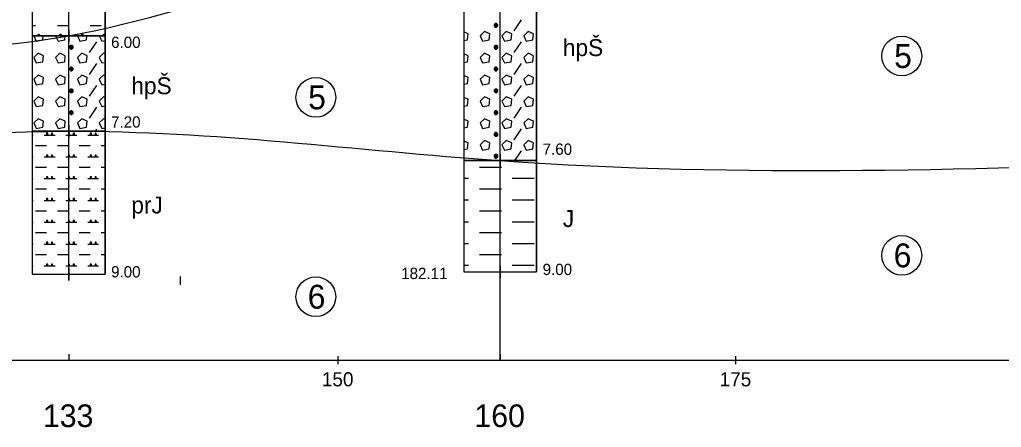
# Model space of a CAD drawing. Extents: x 3042 to 4120, y 576 to 2694.
# Drawn here: x 3349 to 3410.7, y 982.5 to 1008.1 of the extents above; entities that cross this region are included whole.
import ezdxf

# ---------------------------------------------------------------- set-up
doc = ezdxf.new("R2010")
doc.units = 0
for name, color, linetype in [('14', 7, 'Continuous'), ('17', 7, 'Continuous'), ('18', 7, 'Continuous'), ('51', 7, 'Continuous'), ('52', 7, 'Continuous'), ('53', 7, 'Continuous'), ('56', 7, 'Continuous'), ('7', 7, 'Continuous'), ('pomocna', 7, 'Continuous'), ('rozhraní', 7, 'Continuous')]:
    doc.layers.add(name, color=color, linetype=linetype)

msp = doc.modelspace()

# ---------------------------------------------------------------- linework, layer by layer
at = {"layer": '18'}
for p, q in [((3379.247, 992.267), (3379.247, 1037.267)), ((3352.127, 991.717), (3352.127, 1037.117)), ((3351.746, 992.117), (3352.508, 992.117)), ((3352.127, 992.498), (3352.127, 991.736)), ((3378.866, 992.267), (3379.628, 992.267)), ((3379.247, 992.648), (3379.247, 991.886)), ((3352.127, 992.098), (3352.127, 991.717)), ((3352.127, 987.098), (3352.127, 986.717)), ((3379.247, 987.098), (3379.247, 986.717))]:
    msp.add_line(p, q, dxfattribs=at)
at = {"layer": '51'}
for p, q in [((3378.977, 1007.656), (3378.977, 1007.884)), ((3380.12, 1007.427), (3380.578, 1008.113)), ((3378.977, 1006.284), (3378.977, 1006.513)), ((3380.12, 1006.055), (3380.578, 1006.741)), ((3378.977, 1004.912), (3378.977, 1005.141)), ((3380.12, 1004.684), (3380.578, 1005.37)), ((3380.12, 1003.312), (3380.578, 1003.998)), ((3378.977, 1003.541), (3378.977, 1003.769)), ((3380.12, 1001.941), (3380.578, 1002.626)), ((3378.977, 1002.169), (3378.977, 1002.398)), ((3378.977, 1000.798), (3378.977, 1001.026)), ((3380.12, 1000.569), (3380.578, 1001.255)), ((3378.977, 999.426), (3378.977, 999.655)), ((3380.167, 999.267), (3380.578, 999.883)), ((3377.949, 998.855), (3378.635, 998.855)), ((3378.635, 998.855), (3379.32, 998.855)), ((3376.961, 998.169), (3377.263, 998.169)), ((3380.006, 998.169), (3380.692, 998.169)), ((3380.692, 998.169), (3381.378, 998.169)), ((3377.949, 997.483), (3378.635, 997.483)), ((3378.635, 997.483), (3379.32, 997.483)), ((3376.961, 996.797), (3377.263, 996.797)), ((3380.006, 996.797), (3380.692, 996.797)), ((3380.692, 996.797), (3381.378, 996.797)), ((3377.949, 996.111), (3378.635, 996.111)), ((3378.635, 996.111), (3379.32, 996.111)), ((3376.961, 995.426), (3377.263, 995.426)), ((3380.006, 995.426), (3380.692, 995.426)), ((3380.692, 995.426), (3381.378, 995.426)), ((3377.949, 994.74), (3378.635, 994.74)), ((3378.635, 994.74), (3379.32, 994.74)), ((3376.961, 994.054), (3377.263, 994.054)), ((3380.006, 994.054), (3380.692, 994.054)), ((3380.692, 994.054), (3381.378, 994.054)), ((3377.949, 993.368), (3378.635, 993.368)), ((3378.635, 993.368), (3379.32, 993.368)), ((3376.961, 992.682), (3377.263, 992.682)), ((3380.006, 992.682), (3380.692, 992.682)), ((3380.692, 992.682), (3381.378, 992.682))]:
    msp.add_line(p, q, dxfattribs=at)
for points in [[(3376.961, 999.267), (3381.533, 999.267), (3381.533, 1013.767), (3376.961, 1013.767)], [(3349.841, 1007.117), (3354.413, 1007.117), (3354.413, 1013.117), (3349.841, 1013.117)], [(3349.841, 1001.117), (3354.413, 1001.117), (3354.413, 1007.117), (3349.841, 1007.117)], [(3349.841, 992.117), (3354.413, 992.117), (3354.413, 1001.117), (3349.841, 1001.117)], [(3376.961, 992.267), (3381.533, 992.267), (3381.533, 999.267), (3376.961, 999.267)]]:
    msp.add_lwpolyline(points, close=True, dxfattribs=at)
for points in [[(3349.841, 1007.77), (3350.049, 1007.77)], [(3351.421, 1007.77), (3352.107, 1007.77)], [(3353.478, 1007.77), (3354.164, 1007.77)], [(3378.939, 1007.884), (3378.863, 1007.808), (3378.863, 1007.732), (3378.939, 1007.656), (3379.016, 1007.656), (3379.092, 1007.732), (3379.092, 1007.808), (3379.016, 1007.884), (3378.939, 1007.884), (3379.092, 1007.732), (3378.863, 1007.732), (3379.016, 1007.884)], [(3349.937, 1007.117), (3350.087, 1006.779), (3350.506, 1006.856), (3350.532, 1007.117)], [(3350.202, 1007.198), (3350.125, 1007.122), (3350.125, 1007.117)], [(3350.196, 1007.117), (3350.278, 1007.198)], [(3350.354, 1007.117), (3350.354, 1007.122), (3350.278, 1007.198), (3350.202, 1007.198), (3350.283, 1007.117)], [(3350.24, 1007.117), (3350.24, 1007.198)], [(3351.309, 1007.117), (3351.459, 1006.779), (3351.878, 1006.856), (3351.904, 1007.117)], [(3351.573, 1007.198), (3351.497, 1007.122), (3351.497, 1007.117)], [(3351.568, 1007.117), (3351.649, 1007.198)], [(3351.726, 1007.117), (3351.726, 1007.122), (3351.649, 1007.198), (3351.573, 1007.198), (3351.655, 1007.117)], [(3351.611, 1007.117), (3351.611, 1007.198)], [(3352.68, 1007.117), (3352.83, 1006.779), (3353.25, 1006.856), (3353.276, 1007.117)], [(3352.945, 1007.198), (3352.869, 1007.122), (3352.869, 1007.117)], [(3352.94, 1007.117), (3353.021, 1007.198)], [(3353.097, 1007.117), (3353.097, 1007.122), (3353.021, 1007.198), (3352.945, 1007.198), (3353.026, 1007.117)], [(3352.983, 1007.117), (3352.983, 1007.198)], [(3354.052, 1007.117), (3354.202, 1006.779), (3354.413, 1006.818)], [(3354.316, 1007.198), (3354.24, 1007.122), (3354.24, 1007.117)], [(3354.311, 1007.117), (3354.393, 1007.198)], [(3354.413, 1007.178), (3354.393, 1007.198), (3354.316, 1007.198), (3354.398, 1007.117)], [(3354.354, 1007.117), (3354.354, 1007.198)], [(3376.961, 1006.814), (3377.187, 1006.856), (3377.225, 1007.237), (3376.961, 1007.354)], [(3377.987, 1007.122), (3378.139, 1006.779), (3378.558, 1006.856), (3378.596, 1007.237), (3378.254, 1007.389), (3377.987, 1007.122)], [(3379.358, 1007.122), (3379.511, 1006.779), (3379.93, 1006.856), (3379.968, 1007.237), (3379.625, 1007.389), (3379.358, 1007.122)], [(3380.73, 1007.122), (3380.882, 1006.779), (3381.302, 1006.856), (3381.34, 1007.237), (3380.997, 1007.389), (3380.73, 1007.122)], [(3352.259, 1006.513), (3352.183, 1006.436), (3352.183, 1006.36), (3352.259, 1006.284), (3352.335, 1006.284), (3352.411, 1006.36), (3352.411, 1006.436), (3352.335, 1006.513), (3352.259, 1006.513), (3352.411, 1006.36), (3352.183, 1006.36), (3352.335, 1006.513)], [(3352.297, 1006.284), (3352.297, 1006.513)], [(3353.44, 1006.055), (3353.897, 1006.741)], [(3378.939, 1006.513), (3378.863, 1006.436), (3378.863, 1006.36), (3378.939, 1006.284), (3379.016, 1006.284), (3379.092, 1006.36), (3379.092, 1006.436), (3379.016, 1006.513), (3378.939, 1006.513), (3379.092, 1006.36), (3378.863, 1006.36), (3379.016, 1006.513)], [(3349.935, 1005.751), (3350.087, 1005.408), (3350.506, 1005.484), (3350.544, 1005.865), (3350.202, 1006.017), (3349.935, 1005.751)], [(3351.306, 1005.751), (3351.459, 1005.408), (3351.878, 1005.484), (3351.916, 1005.865), (3351.573, 1006.017), (3351.306, 1005.751)], [(3352.678, 1005.751), (3352.83, 1005.408), (3353.25, 1005.484), (3353.288, 1005.865), (3352.945, 1006.017), (3352.678, 1005.751)], [(3354.413, 1005.975), (3354.316, 1006.017), (3354.05, 1005.751)], [(3354.05, 1005.751), (3354.202, 1005.408), (3354.413, 1005.446)], [(3376.961, 1005.443), (3377.187, 1005.484), (3377.225, 1005.865), (3376.961, 1005.982)], [(3377.987, 1005.751), (3378.139, 1005.408), (3378.558, 1005.484), (3378.596, 1005.865), (3378.254, 1006.017), (3377.987, 1005.751)], [(3379.358, 1005.751), (3379.511, 1005.408), (3379.93, 1005.484), (3379.968, 1005.865), (3379.625, 1006.017), (3379.358, 1005.751)], [(3380.73, 1005.751), (3380.882, 1005.408), (3381.302, 1005.484), (3381.34, 1005.865), (3380.997, 1006.017), (3380.73, 1005.751)], [(3352.259, 1005.141), (3352.183, 1005.065), (3352.183, 1004.989), (3352.259, 1004.912), (3352.335, 1004.912), (3352.411, 1004.989), (3352.411, 1005.065), (3352.335, 1005.141), (3352.259, 1005.141), (3352.411, 1004.989), (3352.183, 1004.989), (3352.335, 1005.141)], [(3352.297, 1004.912), (3352.297, 1005.141)], [(3353.44, 1004.684), (3353.897, 1005.37)], [(3378.939, 1005.141), (3378.863, 1005.065), (3378.863, 1004.989), (3378.939, 1004.912), (3379.016, 1004.912), (3379.092, 1004.989), (3379.092, 1005.065), (3379.016, 1005.141), (3378.939, 1005.141), (3379.092, 1004.989), (3378.863, 1004.989), (3379.016, 1005.141)], [(3349.935, 1004.379), (3350.087, 1004.036), (3350.506, 1004.112), (3350.544, 1004.493), (3350.202, 1004.646), (3349.935, 1004.379)], [(3351.306, 1004.379), (3351.459, 1004.036), (3351.878, 1004.112), (3351.916, 1004.493), (3351.573, 1004.646), (3351.306, 1004.379)], [(3352.678, 1004.379), (3352.83, 1004.036), (3353.25, 1004.112), (3353.288, 1004.493), (3352.945, 1004.646), (3352.678, 1004.379)], [(3354.413, 1004.603), (3354.316, 1004.646), (3354.05, 1004.379)], [(3376.961, 1004.071), (3377.187, 1004.112), (3377.225, 1004.493), (3376.961, 1004.611)], [(3377.987, 1004.379), (3378.139, 1004.036), (3378.558, 1004.112), (3378.596, 1004.493), (3378.254, 1004.646), (3377.987, 1004.379)], [(3379.358, 1004.379), (3379.511, 1004.036), (3379.93, 1004.112), (3379.968, 1004.493), (3379.625, 1004.646), (3379.358, 1004.379)], [(3380.73, 1004.379), (3380.882, 1004.036), (3381.302, 1004.112), (3381.34, 1004.493), (3380.997, 1004.646), (3380.73, 1004.379)], [(3353.44, 1003.312), (3353.897, 1003.998)], [(3354.05, 1004.379), (3354.202, 1004.036), (3354.413, 1004.074)], [(3349.935, 1003.007), (3350.087, 1002.665), (3350.506, 1002.741), (3350.544, 1003.122), (3350.202, 1003.274), (3349.935, 1003.007)], [(3351.306, 1003.007), (3351.459, 1002.665), (3351.878, 1002.741), (3351.916, 1003.122), (3351.573, 1003.274), (3351.306, 1003.007)], [(3352.259, 1003.769), (3352.183, 1003.693), (3352.183, 1003.617), (3352.259, 1003.541), (3352.335, 1003.541), (3352.411, 1003.617), (3352.411, 1003.693), (3352.335, 1003.769), (3352.259, 1003.769), (3352.411, 1003.617), (3352.183, 1003.617), (3352.335, 1003.769)], [(3352.297, 1003.541), (3352.297, 1003.769)], [(3352.678, 1003.007), (3352.83, 1002.665), (3353.25, 1002.741), (3353.288, 1003.122), (3352.945, 1003.274), (3352.678, 1003.007)], [(3354.413, 1003.231), (3354.316, 1003.274), (3354.05, 1003.007)], [(3376.961, 1002.7), (3377.187, 1002.741), (3377.225, 1003.122), (3376.961, 1003.239)], [(3377.987, 1003.007), (3378.139, 1002.665), (3378.558, 1002.741), (3378.596, 1003.122), (3378.254, 1003.274), (3377.987, 1003.007)], [(3378.939, 1003.769), (3378.863, 1003.693), (3378.863, 1003.617), (3378.939, 1003.541), (3379.016, 1003.541), (3379.092, 1003.617), (3379.092, 1003.693), (3379.016, 1003.769), (3378.939, 1003.769), (3379.092, 1003.617), (3378.863, 1003.617), (3379.016, 1003.769)], [(3379.358, 1003.007), (3379.511, 1002.665), (3379.93, 1002.741), (3379.968, 1003.122), (3379.625, 1003.274), (3379.358, 1003.007)], [(3380.73, 1003.007), (3380.882, 1002.665), (3381.302, 1002.741), (3381.34, 1003.122), (3380.997, 1003.274), (3380.73, 1003.007)], [(3353.44, 1001.941), (3353.897, 1002.626)], [(3354.05, 1003.007), (3354.202, 1002.665), (3354.413, 1002.703)], [(3352.259, 1002.398), (3352.183, 1002.322), (3352.183, 1002.245), (3352.259, 1002.169), (3352.335, 1002.169), (3352.411, 1002.245), (3352.411, 1002.322), (3352.335, 1002.398), (3352.259, 1002.398), (3352.411, 1002.245), (3352.183, 1002.245), (3352.335, 1002.398)], [(3352.297, 1002.169), (3352.297, 1002.398)], [(3378.939, 1002.398), (3378.863, 1002.322), (3378.863, 1002.245), (3378.939, 1002.169), (3379.016, 1002.169), (3379.092, 1002.245), (3379.092, 1002.322), (3379.016, 1002.398), (3378.939, 1002.398), (3379.092, 1002.245), (3378.863, 1002.245), (3379.016, 1002.398)], [(3349.935, 1001.636), (3350.087, 1001.293), (3350.506, 1001.369), (3350.544, 1001.75), (3350.202, 1001.903), (3349.935, 1001.636)], [(3351.306, 1001.636), (3351.459, 1001.293), (3351.878, 1001.369), (3351.916, 1001.75), (3351.573, 1001.903), (3351.306, 1001.636)], [(3352.678, 1001.636), (3352.83, 1001.293), (3353.25, 1001.369), (3353.288, 1001.75), (3352.945, 1001.903), (3352.678, 1001.636)], [(3354.413, 1001.86), (3354.316, 1001.903), (3354.05, 1001.636)], [(3354.05, 1001.636), (3354.202, 1001.293), (3354.413, 1001.331)], [(3376.961, 1001.328), (3377.187, 1001.369), (3377.225, 1001.75), (3376.961, 1001.868)], [(3377.987, 1001.636), (3378.139, 1001.293), (3378.558, 1001.369), (3378.596, 1001.75), (3378.254, 1001.903), (3377.987, 1001.636)], [(3379.358, 1001.636), (3379.511, 1001.293), (3379.93, 1001.369), (3379.968, 1001.75), (3379.625, 1001.903), (3379.358, 1001.636)], [(3380.73, 1001.636), (3380.882, 1001.293), (3381.302, 1001.369), (3381.34, 1001.75), (3380.997, 1001.903), (3380.73, 1001.636)], [(3349.841, 1000.874), (3349.897, 1000.874)], [(3350.583, 1000.874), (3351.268, 1000.874)], [(3350.735, 1000.988), (3350.735, 1000.912), (3350.811, 1000.912), (3350.811, 1000.988), (3350.735, 1000.988), (3350.811, 1000.912)], [(3351.04, 1000.988), (3351.04, 1000.912), (3351.116, 1000.912), (3351.116, 1000.988), (3351.04, 1000.988), (3351.116, 1000.912)], [(3351.954, 1000.874), (3352.64, 1000.874)], [(3352.107, 1000.988), (3352.107, 1000.912), (3352.183, 1000.912), (3352.183, 1000.988), (3352.107, 1000.988), (3352.183, 1000.912)], [(3352.411, 1000.988), (3352.411, 1000.912), (3352.488, 1000.912), (3352.488, 1000.988), (3352.411, 1000.988), (3352.488, 1000.912)], [(3353.326, 1000.874), (3354.012, 1000.874)], [(3353.478, 1000.988), (3353.478, 1000.912), (3353.554, 1000.912), (3353.554, 1000.988), (3353.478, 1000.988), (3353.554, 1000.912)], [(3353.783, 1000.988), (3353.783, 1000.912), (3353.859, 1000.912), (3353.859, 1000.988), (3353.783, 1000.988), (3353.859, 1000.912)], [(3353.805, 1001.117), (3353.897, 1001.255)], [(3378.939, 1001.026), (3378.863, 1000.95), (3378.863, 1000.874), (3378.939, 1000.798), (3379.016, 1000.798), (3379.092, 1000.874), (3379.092, 1000.95), (3379.016, 1001.026), (3378.939, 1001.026), (3379.092, 1000.874), (3378.863, 1000.874), (3379.016, 1001.026)], [(3350.049, 1000.226), (3350.735, 1000.226)], [(3351.421, 1000.226), (3352.107, 1000.226)], [(3352.792, 1000.226), (3353.478, 1000.226)], [(3354.164, 1000.226), (3354.413, 1000.226)], [(3376.961, 999.957), (3377.187, 999.998), (3377.225, 1000.379), (3376.961, 1000.496)], [(3377.987, 1000.264), (3378.139, 999.921), (3378.558, 999.998), (3378.596, 1000.379), (3378.254, 1000.531), (3377.987, 1000.264)], [(3379.358, 1000.264), (3379.511, 999.921), (3379.93, 999.998), (3379.968, 1000.379), (3379.625, 1000.531), (3379.358, 1000.264)], [(3380.73, 1000.264), (3380.882, 999.921), (3381.302, 999.998), (3381.34, 1000.379), (3380.997, 1000.531), (3380.73, 1000.264)], [(3350.735, 999.617), (3350.735, 999.54), (3350.811, 999.54), (3350.811, 999.617), (3350.735, 999.617), (3350.811, 999.54)], [(3351.04, 999.617), (3351.04, 999.54), (3351.116, 999.54), (3351.116, 999.617), (3351.04, 999.617), (3351.116, 999.54)], [(3352.107, 999.617), (3352.107, 999.54), (3352.183, 999.54), (3352.183, 999.617), (3352.107, 999.617), (3352.183, 999.54)], [(3352.411, 999.617), (3352.411, 999.54), (3352.488, 999.54), (3352.488, 999.617), (3352.411, 999.617), (3352.488, 999.54)], [(3353.478, 999.617), (3353.478, 999.54), (3353.554, 999.54), (3353.554, 999.617), (3353.478, 999.617), (3353.554, 999.54)], [(3353.783, 999.617), (3353.783, 999.54), (3353.859, 999.54), (3353.859, 999.617), (3353.783, 999.617), (3353.859, 999.54)], [(3378.939, 999.655), (3378.863, 999.579), (3378.863, 999.502), (3378.939, 999.426), (3379.016, 999.426), (3379.092, 999.502), (3379.092, 999.579), (3379.016, 999.655), (3378.939, 999.655), (3379.092, 999.502), (3378.863, 999.502), (3379.016, 999.655)], [(3349.841, 999.502), (3349.897, 999.502)], [(3350.583, 999.502), (3351.268, 999.502)], [(3351.954, 999.502), (3352.64, 999.502)], [(3353.326, 999.502), (3354.012, 999.502)], [(3350.049, 998.855), (3350.735, 998.855)], [(3351.421, 998.855), (3352.107, 998.855)], [(3352.792, 998.855), (3353.478, 998.855)], [(3354.164, 998.855), (3354.413, 998.855)], [(3349.841, 998.131), (3349.897, 998.131)], [(3350.583, 998.131), (3351.268, 998.131)], [(3350.735, 998.245), (3350.735, 998.169), (3350.811, 998.169), (3350.811, 998.245), (3350.735, 998.245), (3350.811, 998.169)], [(3351.04, 998.245), (3351.04, 998.169), (3351.116, 998.169), (3351.116, 998.245), (3351.04, 998.245), (3351.116, 998.169)], [(3351.954, 998.131), (3352.64, 998.131)], [(3352.107, 998.245), (3352.107, 998.169), (3352.183, 998.169), (3352.183, 998.245), (3352.107, 998.245), (3352.183, 998.169)], [(3352.411, 998.245), (3352.411, 998.169), (3352.488, 998.169), (3352.488, 998.245), (3352.411, 998.245), (3352.488, 998.169)], [(3353.326, 998.131), (3354.012, 998.131)], [(3353.478, 998.245), (3353.478, 998.169), (3353.554, 998.169), (3353.554, 998.245), (3353.478, 998.245), (3353.554, 998.169)], [(3353.783, 998.245), (3353.783, 998.169), (3353.859, 998.169), (3353.859, 998.245), (3353.783, 998.245), (3353.859, 998.169)], [(3350.049, 997.483), (3350.735, 997.483)], [(3351.421, 997.483), (3352.107, 997.483)], [(3352.792, 997.483), (3353.478, 997.483)], [(3354.164, 997.483), (3354.413, 997.483)], [(3349.841, 996.759), (3349.897, 996.759)], [(3350.583, 996.759), (3351.268, 996.759)], [(3350.735, 996.873), (3350.735, 996.797), (3350.811, 996.797), (3350.811, 996.873), (3350.735, 996.873), (3350.811, 996.797)], [(3351.04, 996.873), (3351.04, 996.797), (3351.116, 996.797), (3351.116, 996.873), (3351.04, 996.873), (3351.116, 996.797)], [(3351.954, 996.759), (3352.64, 996.759)], [(3352.107, 996.873), (3352.107, 996.797), (3352.183, 996.797), (3352.183, 996.873), (3352.107, 996.873), (3352.183, 996.797)], [(3352.411, 996.873), (3352.411, 996.797), (3352.488, 996.797), (3352.488, 996.873), (3352.411, 996.873), (3352.488, 996.797)], [(3353.326, 996.759), (3354.012, 996.759)], [(3353.478, 996.873), (3353.478, 996.797), (3353.554, 996.797), (3353.554, 996.873), (3353.478, 996.873), (3353.554, 996.797)], [(3353.783, 996.873), (3353.783, 996.797), (3353.859, 996.797), (3353.859, 996.873), (3353.783, 996.873), (3353.859, 996.797)], [(3350.049, 996.111), (3350.735, 996.111)], [(3351.421, 996.111), (3352.107, 996.111)], [(3352.792, 996.111), (3353.478, 996.111)], [(3354.164, 996.111), (3354.413, 996.111)], [(3349.841, 995.387), (3349.897, 995.387)], [(3350.583, 995.387), (3351.268, 995.387)], [(3350.735, 995.502), (3350.735, 995.426), (3350.811, 995.426), (3350.811, 995.502), (3350.735, 995.502), (3350.811, 995.426)], [(3351.04, 995.502), (3351.04, 995.426), (3351.116, 995.426), (3351.116, 995.502), (3351.04, 995.502), (3351.116, 995.426)], [(3351.954, 995.387), (3352.64, 995.387)], [(3352.107, 995.502), (3352.107, 995.426), (3352.183, 995.426), (3352.183, 995.502), (3352.107, 995.502), (3352.183, 995.426)], [(3352.411, 995.502), (3352.411, 995.426), (3352.488, 995.426), (3352.488, 995.502), (3352.411, 995.502), (3352.488, 995.426)], [(3353.326, 995.387), (3354.012, 995.387)], [(3353.478, 995.502), (3353.478, 995.426), (3353.554, 995.426), (3353.554, 995.502), (3353.478, 995.502), (3353.554, 995.426)], [(3353.783, 995.502), (3353.783, 995.426), (3353.859, 995.426), (3353.859, 995.502), (3353.783, 995.502), (3353.859, 995.426)], [(3350.049, 994.74), (3350.735, 994.74)], [(3351.421, 994.74), (3352.107, 994.74)], [(3352.792, 994.74), (3353.478, 994.74)], [(3354.164, 994.74), (3354.413, 994.74)], [(3349.841, 994.016), (3349.897, 994.016)], [(3350.583, 994.016), (3351.268, 994.016)], [(3350.735, 994.13), (3350.735, 994.054), (3350.811, 994.054), (3350.811, 994.13), (3350.735, 994.13), (3350.811, 994.054)], [(3351.04, 994.13), (3351.04, 994.054), (3351.116, 994.054), (3351.116, 994.13), (3351.04, 994.13), (3351.116, 994.054)], [(3351.954, 994.016), (3352.64, 994.016)], [(3352.107, 994.13), (3352.107, 994.054), (3352.183, 994.054), (3352.183, 994.13), (3352.107, 994.13), (3352.183, 994.054)], [(3352.411, 994.13), (3352.411, 994.054), (3352.488, 994.054), (3352.488, 994.13), (3352.411, 994.13), (3352.488, 994.054)], [(3353.326, 994.016), (3354.012, 994.016)], [(3353.478, 994.13), (3353.478, 994.054), (3353.554, 994.054), (3353.554, 994.13), (3353.478, 994.13), (3353.554, 994.054)], [(3353.783, 994.13), (3353.783, 994.054), (3353.859, 994.054), (3353.859, 994.13), (3353.783, 994.13), (3353.859, 994.054)], [(3350.049, 993.368), (3350.735, 993.368)], [(3351.421, 993.368), (3352.107, 993.368)], [(3352.792, 993.368), (3353.478, 993.368)], [(3354.164, 993.368), (3354.413, 993.368)], [(3350.735, 992.759), (3350.735, 992.682), (3350.811, 992.682), (3350.811, 992.759), (3350.735, 992.759), (3350.811, 992.682)], [(3351.04, 992.759), (3351.04, 992.682), (3351.116, 992.682), (3351.116, 992.759), (3351.04, 992.759), (3351.116, 992.682)], [(3352.107, 992.759), (3352.107, 992.682), (3352.183, 992.682), (3352.183, 992.759), (3352.107, 992.759), (3352.183, 992.682)], [(3352.411, 992.759), (3352.411, 992.682), (3352.488, 992.682), (3352.488, 992.759), (3352.411, 992.759), (3352.488, 992.682)], [(3353.478, 992.759), (3353.478, 992.682), (3353.554, 992.682), (3353.554, 992.759), (3353.478, 992.759), (3353.554, 992.682)], [(3353.783, 992.759), (3353.783, 992.682), (3353.859, 992.682), (3353.859, 992.759), (3353.783, 992.759), (3353.859, 992.682)], [(3349.841, 992.644), (3349.897, 992.644)], [(3350.583, 992.644), (3351.268, 992.644)], [(3351.954, 992.644), (3352.64, 992.644)], [(3353.326, 992.644), (3354.012, 992.644)]]:
    msp.add_lwpolyline(points, dxfattribs=at)
at = {"layer": '53'}
for p, q in [((3376.961, 1037.267), (3376.961, 992.267)), ((3381.533, 1037.267), (3381.533, 992.267)), ((3376.961, 999.267), (3381.533, 999.267)), ((3376.961, 992.267), (3381.533, 992.267))]:
    msp.add_line(p, q, dxfattribs=at)
for points in [[(3349.841, 1037.117), (3349.841, 992.117)], [(3354.413, 1037.117), (3354.413, 992.117)], [(3349.841, 1007.117), (3354.413, 1007.117)], [(3349.841, 1001.117), (3354.413, 1001.117)], [(3349.841, 992.117), (3354.413, 992.117)]]:
    msp.add_lwpolyline(points, dxfattribs=at)
at = {"layer": '56'}
for p, q in [((3379.247, 999.648), (3379.247, 998.886)), ((3378.866, 999.267), (3379.628, 999.267)), ((3378.866, 992.267), (3379.628, 992.267)), ((3379.247, 992.648), (3379.247, 991.886))]:
    msp.add_line(p, q, dxfattribs=at)
for points in [[(3351.746, 1007.117), (3352.508, 1007.117)], [(3352.127, 1007.498), (3352.127, 1006.736)], [(3352.127, 1001.498), (3352.127, 1000.736)], [(3351.746, 1001.117), (3352.508, 1001.117)], [(3351.746, 992.117), (3352.508, 992.117)], [(3352.127, 992.498), (3352.127, 991.736)]]:
    msp.add_lwpolyline(points, dxfattribs=at)
at = {"layer": '7'}
for p, q in [((3219.057, 986.717), (3446.347, 986.717)), ((3369.057, 986.463), (3369.057, 986.971)), ((3394.057, 986.463), (3394.057, 986.971))]:
    msp.add_line(p, q, dxfattribs=at)
msp.add_lwpolyline([(3359.147, 991.463), (3359.147, 991.971)], dxfattribs=at)
at = {"layer": 'pomocna'}
msp.add_line((3379.247, 986.717), (3379.247, 1039.967), dxfattribs=at)
at = {"layer": 'rozhraní'}
for centre in [(3404.486, 1005.844), (3367.66, 1003.243), (3404.486, 993.307), (3367.66, 990.707)]:
    msp.add_circle(centre, 1.25, dxfattribs=at)
for points in [[(3220.486, 1007.398), (3229.057, 1007.517), (3268.137, 1010.467), (3309.337, 1009.717), (3352.127, 1007.117), (3379.247, 1013.767), (3390.124, 1013.767)], [(3219.084, 996.517), (3229.057, 996.517), (3268.137, 996.467), (3309.337, 996.717), (3352.127, 1001.117), (3379.247, 999.267), (3424.809, 999.267)]]:
    msp.add_spline(points, degree=3, dxfattribs=at)

# ---------------------------------------------------------------- texts
at = {"layer": '14'}
for s, p in [('133', (3350.507, 982.511)), ('160', (3377.627, 982.511))]:
    msp.add_text(s, height=1.4224, dxfattribs=at).set_placement(p)
at = {"layer": '17'}
msp.add_text('182.11', height=0.7112, dxfattribs=at).set_placement((3373.024, 991.815))
at = {"layer": '52'}
for s, height, p in [('6.00', 0.7112, (3354.794, 1006.35)), ('hpŠ', 1.0668, (3383.184, 1005.839)), ('hpŠ', 1.0668, (3356.064, 1003.439)), ('7.20', 0.7112, (3354.794, 1001.34)), ('7.60', 0.7112, (3381.914, 999.63)), ('prJ', 1.0668, (3356.064, 995.939)), ('J', 1.067, (3383.184, 995.089)), ('9.00', 0.7112, (3381.914, 992.069)), ('9.00', 0.7112, (3354.794, 991.919))]:
    msp.add_text(s, height=height, dxfattribs=at).set_placement(p)
at = {"layer": '7'}
for s, p in [('150', (3368.041, 985.072)), ('175', (3393.041, 985.072))]:
    msp.add_text(s, height=0.889, dxfattribs=at).set_placement(p)
at = {"layer": 'rozhraní'}
for s, p in [('5', (3404.005, 1005.094)), ('5', (3367.179, 1002.493)), ('6', (3403.974, 992.557)), ('6', (3367.149, 989.957))]:
    msp.add_text(s, height=1.5, dxfattribs=at).set_placement(p)

doc.saveas('drawing.dxf')
